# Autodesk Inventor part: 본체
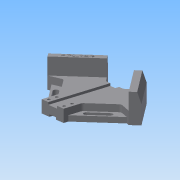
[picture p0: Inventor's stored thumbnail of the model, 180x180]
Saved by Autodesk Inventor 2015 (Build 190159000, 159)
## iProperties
Created: 2020-05
Part Number: 본체
Material: 일반
Document SubType Name: Modeling
Designer: 105687
Density: 1 g/cm^3
Appearance: 기본값
Author: 105687
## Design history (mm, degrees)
sketch "스케치1"
  geometry: L1 (20, 64.853)-(84.853, 0); L2 (84.853, 0)-(35.355, -49.497); L3 (-35.355, -49.497)-(-84.853, 0); L4 (-84.853, 0)-(-20, 64.853); L5 (35.355, -49.497)-(16.005, -30.147); L6 (63.963, 84.853)-(-70.167, 84.853); L7 (20, 64.853)-(-20, 64.853); L8 (0, 64.853)-(0, -30.147); L9 (16.005, -30.147)-(-16.005, -30.147); L10 (-35.355, -49.497)-(-16.005, -30.147); 4 further points
  constraints: 20 end point, 2 horizontal, 2 point on line, 1 coincident, 1 horizontal alignment, 1 midpoint, 1 parallel, 1 vertical, 5 other
  dimensions: "d3" = 64.85281 distance from line of L7 point (0, 0); "d4" = 95 distance of L8.start L8.end; "d6" = 120 distance between parallel lines of L4 L2; "d7" = 10 distance from line of point (0, 0) L10; "d8" = 90 deg angle of L10 L3; "d9" = 90 deg angle of L2 L5; "d10" = 10 distance from line of point (0, 0) L5; "d11" = 30.14719 distance from line of point (0, 0) L9; "d20" = 15 distance from line of point (74.246, 10.607) L2; "d25" = 80 distance from line of L2 point (28.284, 56.569)
extrude "돌출1" new body sketch "스케치1" distance "d12" = 18; taper "d13" = 0 deg
sketch "스케치3"
  geometry: L1 (36.005, 18)-(3.995, 18) reference; L2 (12, 18)-(28, 18); L3 (28, 18)-(28, 14.5); L4 (28, 14.5)-(12, 14.5); L5 (12, 14.5)-(12, 18); L6 (14, 0)-(26, 0); L7 (26, 0)-(26, 3); L8 (26, 3)-(14, 3); L9 (14, 3)-(14, 0); L10 (0, 0)-(40, 0) reference; 7 further points
  constraints: 16 end point, 6 midpoint, 4 parallel, 2 horizontal, 2 perpendicular, 2 vertical alignment, 1 coincident, 1 point on line
  dimensions: "d26" = 16 distance between parallel lines of L3 L5; "d27" = 3.5 distance between parallel lines of L1 L4; "d28" = 12 distance between parallel lines of L7 L9; "d29" = 3 distance between parallel lines of L6 L8
extrude "돌출3" cut sketch "스케치3" stored distance "d30" = 18; taper "d31" = 0 deg
sketch "스케치4"
  geometry: L1 (-74.246, -10.607)-(-52.687, -3.882); L2 (-84.853, 0)-(-20, -64.853) reference; L3 (-74.246, -10.607)-(-20, -64.853); L4 (-35.355, 49.497)-(-84.853, 0) reference; L5 (-20, -64.853)-(-20, -36.569); L6 (-52.687, -3.882)-(-66.829, -18.024); L7 (-52.687, -3.882)-(-20, -36.569); L8 (-52.687, -3.882)-(-2.687, -3.882); 1 further point
  constraints: 12 end point, 3 point on line, 1 collinear, 1 horizontal, 1 perpendicular, 1 vertical
  dimensions: "d32" = 15 distance from line of L1.start L4; "d33" = 25.48997 distance from line of L1.end L4; "d36" = 20 horizontal distance of L3.end point (0, 0); "d43" = 20 distance from line of L1.end L2; "d45" = 45 deg angle of L7 L8
extrude "돌출4" cut sketch "스케치4" stored distance "d38" = 18; taper "d39" = 0 deg
sketch "스케치5"
  geometry: L1 (8, -64.853)-(-8, -64.853) reference; C1 r 2.25 at (-14, -46.853); C2 r 2.25 at (-14, -58.853); 1 further point
  constraints: 2 centre point, 1 vertical alignment
  dimensions: "d40" = 4.5 diameter of C1; "d41" = 4.5 diameter of C2; "d42" = 14 horizontal distance of C2.centre point (0, 0); "d46" = 6 distance from line of C2.centre L1; "d47" = 12 distance of C1.centre C2.centre
extrude "돌출5" cut sketch "스케치5" distance "d48" = 10; taper "d49" = 0 deg
sketch "스케치6"
  geometry: C1 r 2.25 at (0, 0) reference; C2 r 4 at (0, 0); C3 r 2.25 at (0, -12) reference; C4 r 4 at (0, -12); 1 further point
  constraints: 2 centre point, 2 coincident
  dimensions: "d50" = 8 diameter of C2; "d51" = 8 diameter of C4
extrude "돌출6" cut sketch "스케치6" stored distance "d52" = 10; taper "d53" = 0 deg
sketch "스케치7"
  geometry: L1 (0, 18)-(15, 18); L2 (15, 18)-(15, 42); L3 (15, 42)-(5, 42); L4 (0, 27)-(0, 18); L5 (0, 0)-(15, 0) reference; L6 (0, 27)-(5, 42); 1 further point
  constraints: 10 end point, 2 parallel, 1 horizontal, 1 perpendicular
  dimensions: "d55" = 42 distance between parallel lines of L5 L3; "d63" = 5 distance from line of L3.end L4; "d64" = 15 distance between parallel lines of L2 L4; "d65" = 15 distance from line of L4.start L3
extrude "돌출7" join sketch "스케치7" distance "d60" = 70; taper "d61" = 0 deg
sketch "스케치8"
  geometry: L1 (0, 18)-(-15, 18); L2 (-15, 18)-(-15, 42); L3 (-15, 42)-(-5, 42); L4 (0, 27)-(0, 18); L5 (-15, 0)-(0, 0) reference; L6 (0, 27)-(-5, 42); 1 further point
  constraints: 10 end point, 2 parallel, 1 horizontal, 1 perpendicular
  dimensions: "d67" = 42 distance between parallel lines of L5 L3; "d69" = 5 distance from line of L4 L3.end; "d70" = 15 vertical distance of L4.start L3.end; "d71" = 15 distance between parallel lines of L4 L2
extrude "돌출8" join sketch "스케치8" distance "d72" = 70; taper "d73" = 0 deg
node "작업 평면1"
sketch "스케치9"
  geometry: L1 (6, -30.147)-(6, 64.853) reference; L2 (6, 64.853)-(20, 64.853) reference; L3 (20, 64.853)-(20, 36.569) reference; L4 (20, 36.569)-(52.687, 3.882) reference; L5 (52.687, 3.882)-(74.246, 10.607) reference; L6 (74.246, 10.607)-(84.853, 0) reference; L7 (84.853, 0)-(35.355, -49.497) reference; L8 (35.355, -49.497)-(16.005, -30.147) reference; L9 (16.005, -30.147)-(6, -30.147) reference; L10 (-6, 64.853)-(-6, -30.147) reference; L11 (-6, -30.147)-(-16.005, -30.147) reference; L12 (-16.005, -30.147)-(-35.355, -49.497) reference; L13 (-35.355, -49.497)-(-84.853, 0) reference; L14 (-84.853, 0)-(-74.246, 10.607) reference; L15 (-74.246, 10.607)-(-52.687, 3.882) reference; L16 (-52.687, 3.882)-(-20, 36.569) reference; L17 (-20, 36.569)-(-20, 64.853) reference; L18 (-20, 64.853)-(-6, 64.853) reference; L19 (74.246, 10.607)-(20, 64.853); L20 (68.856, 8.925)-(20, 57.782); L21 (68.856, 8.925)-(52.687, 3.882); L22 (52.687, 3.882)-(20, 36.569); L23 (20, 36.569)-(20, 57.782); C1 r 4 at (-14, 58.853) reference; C2 r 4 at (-14, 46.853) reference; C3 r 4 at (14, 46.853) reference; C4 r 4 at (14, 58.853) reference; 1 further point
  constraints: 10 end point, 2 collinear, 2 point on line, 1 parallel
  dimensions: "d76" = 15 distance between parallel lines of L20 L4
extrude "돌출9" join sketch "스케치9" distance "d77" = 8; taper "d78" = 0 deg
sketch "스케치10"
  geometry: L1 (-84.853, 0)-(-35.355, 49.497) reference; L2 (-74.246, -10.607)-(-81.317, -3.536) reference; L3 (-52.326, -21.213)-(-32.527, -41.012); L4 (-46.492, -15.745)-(-26.871, -35.354); L5 (-68.856, -8.925)-(-20, -57.782) reference; A1 r 4 centre (-49.497, -18.385) between (-46.492, -15.745) and (-52.326, -21.213); A2 r 4 centre (-29.698, -38.184) between (-32.527, -41.012) and (-26.871, -35.354); 1 further point
  constraints: 4 end point, 4 point on circle, 2 centre point, 1 tangent
  dimensions: "d79" = 8 diameter of A1; "d80" = 8 diameter of A2; "d81" = 38 distance from line of A1.centre L1; "d82" = 66 distance from line of A2.centre L1; "d83" = 12 distance from line of A1.centre L2; "d84" = 12 distance from line of L2 A2.centre; "d85" = 0.017318 deg angle of L4 L3; "d86" = 0.017318 deg angle of L5 L4; "d87" = 4 distance from line of L3 A1.centre
extrude "돌출10" cut sketch "스케치10" stored distance "d88" = 8; taper "d89" = 0 deg
sketch "스케치11"
  geometry: L1 (26.871, 35.354)-(46.492, 15.745) reference; L2 (52.326, 21.213)-(32.527, 41.012) reference; L3 (6, -30.147)-(6, 64.853) reference; L4 (6, 64.853)-(20, 64.853) reference; L5 (20, 64.853)-(20, 57.782) reference; L6 (20, 57.782)-(68.856, 8.925) reference; L7 (68.856, 8.925)-(74.246, 10.607) reference; L8 (74.246, 10.607)-(84.853, 0) reference; L9 (84.853, 0)-(35.355, -49.497) reference; L10 (35.355, -49.497)-(16.005, -30.147) reference; L11 (16.005, -30.147)-(6, -30.147) reference; L12 (-6, 64.853)-(-6, -30.147) reference; L13 (-6, -30.147)-(-16.005, -30.147) reference; L14 (-16.005, -30.147)-(-35.355, -49.497) reference; L15 (-35.355, -49.497)-(-84.853, 0) reference; L16 (-84.853, 0)-(-74.246, 10.607) reference; L17 (-74.246, 10.607)-(-52.687, 3.882) reference; L18 (-52.687, 3.882)-(-20, 36.569) reference; L19 (-20, 36.569)-(-20, 64.853) reference; L20 (-20, 64.853)-(-6, 64.853) reference; L21 (-20, 64.853)-(-74.246, 10.607); L22 (-20, 57.782)-(-20, 36.569); L23 (-20, 36.569)-(-52.687, 3.882); L24 (-52.687, 3.882)-(-68.856, 8.925); L25 (-20, 57.782)-(-68.856, 8.925); C1 r 4 at (-14, 58.853) reference; C2 r 4 at (-14, 46.853) reference; C3 r 4 at (14, 46.853) reference; C4 r 4 at (14, 58.853) reference; A1 r 4 centre (49.497, 18.385) between (46.492, 15.745) and (52.326, 21.213) reference; A2 r 4 centre (29.698, 38.184) between (32.527, 41.012) and (26.871, 35.354) reference; 1 further point
  constraints: 10 end point, 2 collinear, 2 point on line, 1 parallel
  dimensions: "d91" = 15 distance between parallel lines of L18 L25
extrude "돌출11" join sketch "스케치11" distance "d92" = 8; taper "d93" = 0 deg
sketch "스케치12"
  geometry: L1 (0, 0)-(70, 0) reference; L2 (70, 10)-(70, 0) reference; 2 further points
  constraints: 1 other
  dimensions: "d94" = 5 distance from line of point (35, 5) L1; "d95" = 35 distance from line of point (35, 5) L2
feature "엠보싱1" sketch "스케치12" dims "d3" = 64.85281, "d4" = 95, "d6" = 120, "d7" = 10, "d8" = 90 deg, "d9" = 90 deg, "d10" = 10, "d11" = 30.14719, "d20" = 15, "d25" = 80, "d26" = 16, "d27" = 3.5, "d96" = 0.5, "d97" = 0
fillet "모깎기1" dims "d98" = 5
node "솔리드1"
mirror "대칭1"
mirror "대칭2"
mirror "대칭3"
node "절단 모서리 투영1"
node "절단 모서리 투영2"
other parameters: "d74" = 0, "d75" = 5, "d90" = 5
